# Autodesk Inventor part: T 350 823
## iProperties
Company: Mayer & Müller AG Schaltgeräte
Created: 2005-12
Part Number: T 350 823
Material: 2.0060.30
Document SubType Name: Sheet Metal
Designer: I.Baliuc
Manufacturer: Standard
Standards Organization: Custom
Description: Spulenanschlußfahne
Density: 8.94 g/cm^3
Sheet Metal Rule: Standard
HalbzeugNorm: DIN 1759
Zweck: zum Lichtbogenabreißer
Abmessung: 80x5-85,5
Author: T.Messerschmitt
Revision Number: 350823
Keywords: 382208
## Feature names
1. Bohrung_Ø10.2 [Hole]
2. Bohrung_Ø3 [Hole]
3. Bohrung3 [Hole]
4. Grobblech1
5. Biegung1
6. Grobblech2
7. Biegung2
8. ExtrusionAbwicklung2
